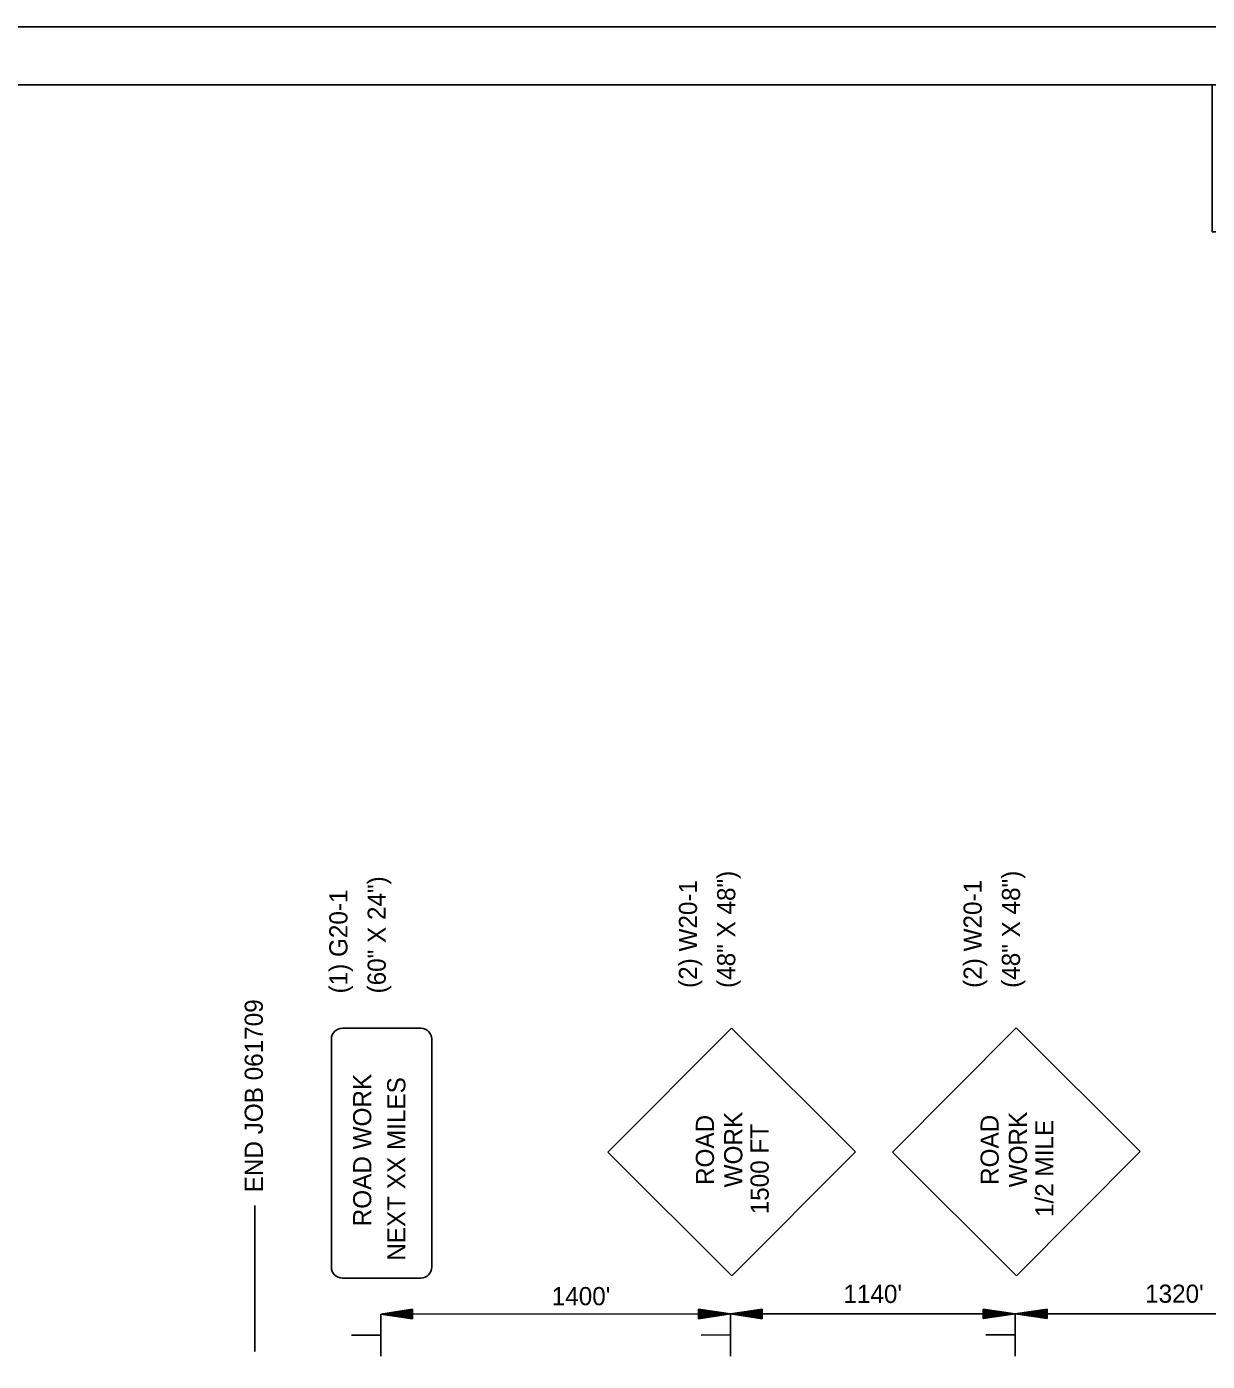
# Model space of a CAD drawing. Extents: x 1397271 to 1411271, y 376395 to 377888.
# Drawn here: x 1398438 to 1398993, y 377260 to 377888 of the extents above; entities that cross this region are included whole.
import ezdxf

# ---------------------------------------------------------------- set-up
doc = ezdxf.new("R2010")
doc.units = 0
for name, color, linetype in [('Default', 7, 'Continuous'), ('R_Border', 7, 'Continuous'), ('R_Draft', 7, 'Continuous'), ('R_MOT', 7, 'Continuous'), ('R_No Plot', 7, 'Continuous')]:
    doc.layers.add(name, color=color, linetype=linetype)

msp = doc.modelspace()

# ---------------------------------------------------------------- linework, layer by layer
at = {"layer": 'Default'}
for p, q in [((1398545.15, 377264.91), (1398545.15, 377333.67)), ((1398768.72, 377282.64), (1398604.33, 377282.61)), ((1398902.58, 377282.68), (1398768.72, 377282.64)), ((1399057.58, 377282.68), (1398902.58, 377282.68))]:
    msp.add_line(p, q, dxfattribs=at)
at = {"layer": 'R_Border'}
msp.add_line((1397357.73, 377860.72), (1399571.03, 377860.72), dxfattribs=at)
at = {"layer": 'R_Draft'}
for p, q in [((1398619.33, 377284.86), (1398604.33, 377282.61)), ((1398619.33, 377280.36), (1398619.33, 377284.86)), ((1398753.72, 377284.89), (1398768.72, 377282.64)), ((1398753.72, 377284.89), (1398753.72, 377280.39)), ((1398783.72, 377284.89), (1398768.72, 377282.64)), ((1398783.72, 377280.39), (1398783.72, 377284.89)), ((1398887.58, 377284.93), (1398902.58, 377282.68)), ((1398887.58, 377284.93), (1398887.58, 377280.43)), ((1398917.58, 377284.93), (1398902.58, 377282.68)), ((1398917.58, 377280.43), (1398917.58, 377284.93)), ((1398619.33, 377280.36), (1398604.33, 377282.61)), ((1398619.33, 377284.48), (1398606.83, 377282.61)), ((1398619.33, 377280.73), (1398606.83, 377282.61)), ((1398619.33, 377284.1), (1398609.41, 377282.61)), ((1398619.33, 377281.12), (1398609.41, 377282.61)), ((1398619.33, 377283.73), (1398611.91, 377282.61)), ((1398619.33, 377281.49), (1398611.91, 377282.61)), ((1398619.33, 377283.34), (1398614.45, 377282.61)), ((1398619.33, 377281.88), (1398614.45, 377282.61)), ((1398619.33, 377282.96), (1398616.96, 377282.61)), ((1398619.33, 377282.26), (1398616.96, 377282.61)), ((1398753.72, 377284.52), (1398766.22, 377282.64)), ((1398753.72, 377284.13), (1398763.64, 377282.64)), ((1398753.72, 377283.76), (1398761.14, 377282.64)), ((1398753.72, 377283.37), (1398758.6, 377282.64)), ((1398753.72, 377282.99), (1398756.09, 377282.64)), ((1398753.72, 377280.39), (1398768.72, 377282.64)), ((1398753.72, 377281.91), (1398758.6, 377282.64)), ((1398753.72, 377281.15), (1398763.64, 377282.64)), ((1398753.72, 377280.77), (1398766.22, 377282.64)), ((1398753.72, 377281.52), (1398761.14, 377282.64)), ((1398753.72, 377282.29), (1398756.09, 377282.64)), ((1398783.72, 377280.39), (1398768.72, 377282.64)), ((1398783.72, 377284.52), (1398771.23, 377282.64)), ((1398783.72, 377280.77), (1398771.23, 377282.64)), ((1398783.72, 377284.13), (1398773.81, 377282.64)), ((1398783.72, 377281.15), (1398773.81, 377282.64)), ((1398783.72, 377283.76), (1398776.31, 377282.64)), ((1398783.72, 377281.52), (1398776.31, 377282.64)), ((1398783.72, 377283.38), (1398778.85, 377282.64)), ((1398783.72, 377281.91), (1398778.85, 377282.64)), ((1398783.72, 377282.99), (1398781.35, 377282.64)), ((1398783.72, 377282.29), (1398781.35, 377282.64)), ((1398887.58, 377284.56), (1398900.08, 377282.68)), ((1398887.58, 377284.17), (1398897.5, 377282.68)), ((1398887.58, 377283.8), (1398895, 377282.68)), ((1398887.58, 377283.41), (1398892.46, 377282.68)), ((1398887.58, 377283.03), (1398889.95, 377282.68)), ((1398887.58, 377280.43), (1398902.58, 377282.68)), ((1398887.58, 377281.95), (1398892.46, 377282.68)), ((1398887.58, 377281.19), (1398897.5, 377282.68)), ((1398887.58, 377280.81), (1398900.08, 377282.68)), ((1398887.58, 377281.56), (1398895, 377282.68)), ((1398887.58, 377282.33), (1398889.95, 377282.68)), ((1398917.58, 377280.43), (1398902.58, 377282.68)), ((1398917.58, 377284.56), (1398905.09, 377282.68)), ((1398917.58, 377280.81), (1398905.09, 377282.68)), ((1398917.58, 377284.17), (1398907.67, 377282.68)), ((1398917.58, 377281.19), (1398907.67, 377282.68)), ((1398917.58, 377283.8), (1398910.17, 377282.68)), ((1398917.58, 377281.56), (1398910.17, 377282.68)), ((1398917.58, 377283.42), (1398912.71, 377282.68)), ((1398917.58, 377281.95), (1398912.71, 377282.68)), ((1398917.58, 377283.03), (1398915.21, 377282.68)), ((1398917.58, 377282.33), (1398915.21, 377282.68))]:
    msp.add_line(p, q, dxfattribs=at)
at = {"layer": 'R_MOT'}
for p, q in [((1398623.2, 377417.01), (1398586.3, 377417.01)), ((1398769.19, 377417.1), (1398711.08, 377358.73)), ((1398769.19, 377417.1), (1398827.56, 377358.94)), ((1398903.05, 377417.14), (1398844.94, 377358.77)), ((1398903.05, 377417.14), (1398961.42, 377358.98)), ((1398581.14, 377411.85), (1398581.14, 377304.68)), ((1398628.36, 377411.85), (1398628.36, 377304.68)), ((1398711.08, 377358.73), (1398769.4, 377300.57)), ((1398827.56, 377358.94), (1398769.4, 377300.57)), ((1398844.94, 377358.77), (1398903.26, 377300.61)), ((1398961.42, 377358.98), (1398903.26, 377300.61)), ((1398623.2, 377299.51), (1398586.3, 377299.51)), ((1398604.33, 377282.61), (1398604.42, 377262.75)), ((1398768.72, 377282.64), (1398768.81, 377262.79)), ((1398902.58, 377282.68), (1398902.67, 377262.83)), ((1398604.37, 377272.73), (1398590.53, 377272.67)), ((1398768.77, 377272.76), (1398754.93, 377272.7)), ((1398902.63, 377272.8), (1398888.79, 377272.74))]:
    msp.add_line(p, q, dxfattribs=at)
for centre, start, end in [((1398586.3, 377411.85), 90, 180), ((1398623.19, 377411.85), 0, 90), ((1398586.3, 377304.68), 180, 270), ((1398623.19, 377304.68), 270, 0)]:
    msp.add_arc(centre, 5.17, start, end, dxfattribs=at)
at = {"layer": 'R_No Plot'}
msp.add_line((1397270.92, 377887.98), (1399604.3, 377887.98), dxfattribs=at)
for points in [[(1397270.87, 377887.98), (1399604.3, 377887.98), (1399604.3, 376394.59), (1397270.87, 376394.59)], [(1398995.2, 377860.72), (1398995.2, 377791.56), (1399245.33, 377791.56), (1399245.33, 377771.12), (1399407.73, 377771.12), (1399407.73, 377600.79), (1399571.03, 377600.79), (1399571.03, 376422.47), (1397357.73, 376422.47), (1397357.73, 377860.72)]]:
    msp.add_lwpolyline(points, close=True, dxfattribs=at)

# ---------------------------------------------------------------- texts
at = {"layer": 'Default'}
msp.add_text('END JOB 061709', height=8.54, rotation=90, dxfattribs=at).set_placement((1398548.9, 377339.83))
for s, p in [("1400'", (1398684.71, 377286.75)), ("1140'", (1398821.86, 377287.8)), ("1320'", (1398963.69, 377287.89))]:
    msp.add_text(s, height=8.54, dxfattribs=at).set_placement(p)
at = {"layer": 'R_MOT'}
for s, rotation, p in [('(60" X 24")', 90, (1398606.69, 377433.36)), ('(2) W20-1', 90, (1398753.03, 377435.95)), ('(48" X 48")', 90, (1398771.03, 377435.95)), ('(2) W20-1', 90, (1398886.89, 377435.99)), ('(48" X 48")', 90, (1398904.89, 377435.99)), ('(1) G20-1', 90, (1398588.69, 377433.36)), ('ROAD WORK', 90, (1398599.87, 377323.86)), (' NEXT XX MILES', 90, (1398615.91, 377304.5)), ('ROAD', 90.10045, (1398761.04, 377343.27)), ('WORK', 90.10034, (1398774.35, 377342.16)), ('ROAD', 90.10045, (1398894.9, 377343.31)), ('WORK', 90.10034, (1398908.21, 377342.2)), (' 1/2 MILE', 90.0995, (1398920.64, 377325.05)), (' 1500 FT', 90.0995, (1398786.77, 377326.32))]:
    msp.add_text(s, height=8.54, rotation=rotation, dxfattribs=at).set_placement(p)

doc.saveas('drawing.dxf')
